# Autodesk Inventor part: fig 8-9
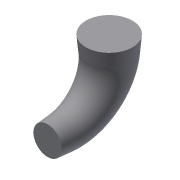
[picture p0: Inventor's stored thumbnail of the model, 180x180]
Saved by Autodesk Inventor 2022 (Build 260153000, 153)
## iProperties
Created: 2001-12
Part Number: fig 8-9
Document SubType Name: Modeling
Designer: CADSoft
Density: 1 g/cm^3
Material: Generic
Appearance: Default
Control State: 0
Master: False
Checked Out: False
Shininess: 77.0
Length Units: 11269
Angle Units: 11279
Time Units: 11290
Mass Units: 11283
Length Display Precision: 3
Angle Display Precision: 2
Density: 0.0
Volumn: 0.0
Area: 0.0
PropertySet Name: Model Information
Author: CADSoft
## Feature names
1. Sweep7
## Parameters: d4 = 15 mm, d5 = 15 mm, d13 = 5 deg, d14 = 0
